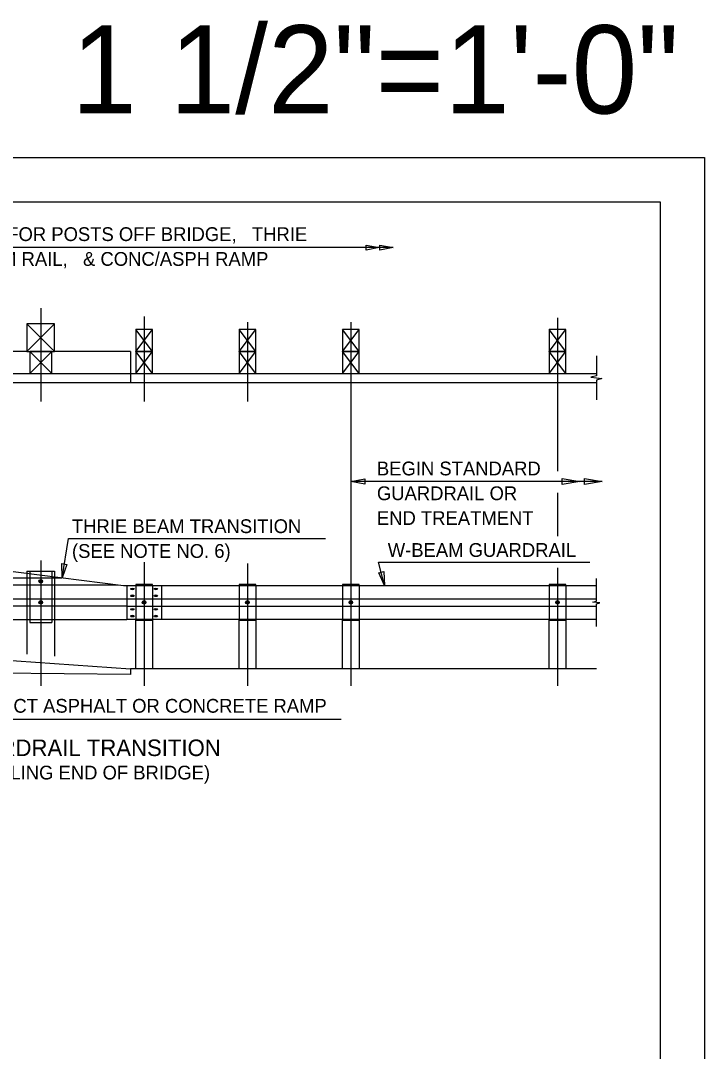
# Model space of a CAD drawing. Extents: x 0 to 22.7, y 0 to 15.7.
# Drawn here: x 17.5 to 22.67, y 7.91 to 15.7 of the extents above; entities that cross this region are included whole.
import ezdxf

# ---------------------------------------------------------------- set-up
doc = ezdxf.new("R2010")
doc.units = 0
for name, color, linetype in [('BORDER_ANNO_Cutsheet', 7, 'Continuous'), ('BRDG_ANNO_Anno-Sheet', 7, 'Continuous'), ('BRDG_ANNO_General-Notes', 7, 'Continuous'), ('BRDG_BASE_Dtlctrln', 7, 'Continuous'), ('BRDG_BASE_Phtline', 7, 'Continuous')]:
    doc.layers.add(name, color=color, linetype=linetype)

msp = doc.modelspace()

# ---------------------------------------------------------------- linework, layer by layer
at = {"layer": 'BORDER_ANNO_Cutsheet'}
msp.add_lwpolyline([(0, 14.6667), (22.6667, 14.6667), (22.6667, 0), (0, 0)], close=True, dxfattribs=at)
at = {"layer": 'BRDG_ANNO_Anno-Sheet'}
msp.add_lwpolyline([(1, 14.3333), (22.3333, 14.3333), (22.3333, 0.3333), (1, 0.3333)], close=True, dxfattribs=at)
at = {"layer": 'BRDG_ANNO_General-Notes'}
for p, q in [((20.3134, 13.9864), (14.4561, 13.9864)), ((20.1093, 13.9677), (20.1093, 14.0052)), ((20.1093, 14.0052), (20.2093, 13.9864)), ((20.2093, 13.9864), (20.1093, 13.9677)), ((20.2134, 13.9677), (20.2134, 14.0052)), ((20.2134, 14.0052), (20.3134, 13.9864)), ((20.3134, 13.9864), (20.2134, 13.9677)), ((19.994, 12.2181), (20.099, 12.2378)), ((20.099, 12.2378), (20.099, 12.1984)), ((21.8945, 12.2181), (19.994, 12.2181)), ((20.099, 12.1984), (19.994, 12.2181)), ((17.8086, 11.5971), (17.8474, 11.5906)), ((17.8107, 11.4903), (17.8086, 11.5971)), ((17.8474, 11.5906), (17.8107, 11.4903)), ((20.2045, 11.5271), (20.2426, 11.5369)), ((20.2426, 11.5369), (20.2498, 11.4303)), ((20.2498, 11.4303), (20.2045, 11.5271)), ((16.7052, 10.4213), (19.9203, 10.4213))]:
    msp.add_line(p, q, dxfattribs=at)
for points in [[(21.5915, 12.2402), (21.7248, 12.2181), (21.5915, 12.1961)], [(21.7611, 12.2402), (21.8945, 12.2181), (21.7611, 12.1961)]]:
    msp.add_lwpolyline(points, close=True, dxfattribs=at)
for points in [[(17.8107, 11.4903), (17.8602, 11.7862), (19.8026, 11.7862)], [(20.2039, 11.6081), (21.7996, 11.6081)], [(20.2498, 11.4303), (20.2039, 11.6081)]]:
    msp.add_lwpolyline(points, dxfattribs=at)
at = {"layer": 'BRDG_BASE_Dtlctrln'}
for p, q in [((17.6502, 13.5289), (17.6502, 12.8218)), ((18.4315, 13.464), (18.4315, 12.8218)), ((19.2127, 13.4211), (19.2127, 12.8218)), ((19.994, 13.4211), (19.994, 10.6736)), ((21.5565, 13.4545), (21.5565, 12.2957)), ((21.5565, 12.1317), (21.5565, 11.8034)), ((17.6502, 11.621), (17.6502, 10.6736)), ((18.4315, 11.6089), (18.4315, 10.6736)), ((19.2127, 11.5986), (19.2127, 10.6736)), ((21.5565, 11.5645), (21.5565, 10.6736))]:
    msp.add_line(p, q, dxfattribs=at)
at = {"layer": 'BRDG_BASE_Phtline'}
for p, q in [((17.546, 13.2011), (17.7544, 13.4095)), ((17.7544, 13.2011), (17.546, 13.4095)), ((18.369, 13.2011), (18.494, 13.3678)), ((18.494, 13.2011), (18.369, 13.3678)), ((19.1502, 13.2011), (19.2752, 13.3678)), ((19.2752, 13.2011), (19.1502, 13.3678)), ((19.9315, 13.2011), (20.0565, 13.3678)), ((20.0565, 13.2011), (19.9315, 13.3678)), ((21.494, 13.2011), (21.619, 13.3678)), ((21.619, 13.2011), (21.494, 13.3678)), ((17.546, 13.2011), (16.9731, 13.2011)), ((17.5669, 13.0345), (17.7335, 13.2011)), ((17.7335, 13.0345), (17.5669, 13.2011)), ((18.3273, 13.2011), (17.7544, 13.2011)), ((18.3273, 13.2011), (18.3273, 13.0345)), ((18.369, 13.0345), (18.494, 13.2011)), ((18.494, 13.0345), (18.369, 13.2011)), ((19.1502, 13.0345), (19.2752, 13.2011)), ((19.2752, 13.0345), (19.1502, 13.2011)), ((19.9315, 13.0345), (20.0565, 13.2011)), ((20.0565, 13.0345), (19.9315, 13.2011)), ((21.494, 13.0345), (21.619, 13.2011)), ((21.619, 13.0345), (21.494, 13.2011)), ((16.7387, 13.0345), (21.8499, 13.0345)), ((18.3273, 13.0345), (18.3273, 12.9668)), ((16.7387, 12.9668), (21.8499, 12.9668)), ((17.0252, 11.5918), (18.2752, 11.4303)), ((17.546, 11.5388), (17.7544, 11.5388)), ((17.546, 11.5388), (17.546, 11.5245)), ((17.5669, 11.5388), (17.5669, 11.5218)), ((17.7335, 11.5388), (17.7335, 11.5003)), ((17.7544, 11.5388), (17.7544, 11.4976)), ((16.9992, 11.4904), (17.8105, 11.4904)), ((17.546, 11.5245), (17.546, 11.1751)), ((17.5669, 11.5218), (17.5669, 11.1751)), ((17.7335, 11.5003), (17.7335, 11.1751)), ((17.7544, 11.4976), (17.7544, 11.1751)), ((16.9992, 11.4354), (18.2359, 11.4354)), ((18.2752, 11.4303), (21.8499, 11.4303)), ((18.3012, 11.4303), (18.3012, 11.1751)), ((18.369, 11.4303), (18.369, 11.1751)), ((18.494, 11.4303), (18.494, 11.1751)), ((18.5617, 11.4303), (18.5617, 11.1751)), ((19.1502, 11.4303), (19.1502, 11.1751)), ((19.2752, 11.4303), (19.2752, 11.1751)), ((19.9315, 11.4303), (19.9315, 11.1751)), ((20.0565, 11.4303), (20.0565, 11.1751)), ((21.494, 11.4303), (21.494, 11.1751)), ((21.619, 11.4303), (21.619, 11.1751)), ((16.9992, 11.3315), (18.3012, 11.3315)), ((18.3012, 11.3302), (21.8499, 11.3302)), ((16.9992, 11.2766), (18.3012, 11.2766)), ((18.3012, 11.2753), (21.8499, 11.2753)), ((16.9992, 11.1751), (18.3012, 11.1751)), ((17.546, 11.1751), (17.546, 10.9115)), ((17.5669, 11.1751), (17.5669, 11.1504)), ((17.5669, 11.1504), (17.7335, 11.1504)), ((17.7335, 11.1751), (17.7335, 11.1504)), ((17.7544, 11.1751), (17.7544, 10.8967)), ((21.8499, 11.1751), (18.3012, 11.1751)), ((18.369, 10.8001), (18.369, 11.166)), ((18.494, 11.166), (18.494, 10.8001)), ((19.1502, 10.8001), (19.1502, 11.166)), ((19.2752, 11.166), (19.2752, 10.8001)), ((19.9315, 10.8001), (19.9315, 11.166)), ((20.0565, 11.166), (20.0565, 10.8001)), ((21.494, 10.8001), (21.494, 11.166)), ((21.619, 11.166), (21.619, 10.8001)), ((15.0244, 11.0356), (18.3273, 10.8001)), ((18.3273, 10.7584), (15.0244, 10.794)), ((21.8499, 10.8001), (18.3273, 10.8001)), ((18.3273, 10.8001), (18.3273, 10.7584))]:
    msp.add_line(p, q, dxfattribs=at)
for points in [[(17.546, 13.2011), (17.7544, 13.2011), (17.7544, 13.4095), (17.546, 13.4095)], [(18.369, 13.2011), (18.494, 13.2011), (18.494, 13.3678), (18.369, 13.3678)], [(19.1502, 13.2011), (19.2752, 13.2011), (19.2752, 13.3678), (19.1502, 13.3678)], [(19.9315, 13.2011), (20.0565, 13.2011), (20.0565, 13.3678), (19.9315, 13.3678)], [(21.494, 13.2011), (21.619, 13.2011), (21.619, 13.3678), (21.494, 13.3678)], [(17.5669, 13.0345), (17.7335, 13.0345), (17.7335, 13.2011), (17.5669, 13.2011)], [(18.369, 13.0345), (18.494, 13.0345), (18.494, 13.2011), (18.369, 13.2011)], [(19.1502, 13.0345), (19.2752, 13.0345), (19.2752, 13.2011), (19.1502, 13.2011)], [(19.9315, 13.0345), (20.0565, 13.0345), (20.0565, 13.2011), (19.9315, 13.2011)], [(21.494, 13.0345), (21.619, 13.0345), (21.619, 13.2011), (21.494, 13.2011)]]:
    msp.add_lwpolyline(points, close=True, dxfattribs=at)
for points in [[(21.8499, 13.1673), (21.8499, 13.0162), (21.8082, 13.0058), (21.8499, 13.0006), (21.8916, 12.9954), (21.8499, 12.985), (21.8499, 12.834)], [(21.8499, 11.1204), (21.8499, 11.293), (21.8759, 11.2995), (21.8499, 11.3027), (21.8239, 11.306), (21.8499, 11.3125), (21.8499, 11.485)], [(18.494, 11.4303), (18.494, 11.4394), (18.369, 11.4394), (18.369, 11.4303)], [(19.2752, 11.4303), (19.2752, 11.4394), (19.1502, 11.4394), (19.1502, 11.4303)], [(20.0565, 11.4303), (20.0565, 11.4394), (19.9315, 11.4394), (19.9315, 11.4303)], [(21.619, 11.4303), (21.619, 11.4394), (21.494, 11.4394), (21.494, 11.4303)], [(18.494, 11.1751), (18.494, 11.166), (18.369, 11.166), (18.369, 11.1751)], [(19.2752, 11.1751), (19.2752, 11.166), (19.1502, 11.166), (19.1502, 11.1751)], [(20.0565, 11.1751), (20.0565, 11.166), (19.9315, 11.166), (19.9315, 11.1751)], [(21.619, 11.1751), (21.619, 11.166), (21.494, 11.166), (21.494, 11.1751)]]:
    msp.add_lwpolyline(points, dxfattribs=at)
for centre, radius in [((17.6502, 11.4629), 0.0137), ((17.6502, 11.4629), 0.00651), ((17.6502, 11.304), 0.0137), ((17.6502, 11.304), 0.00651), ((18.4314, 11.304), 0.0137), ((18.4314, 11.304), 0.00651), ((19.2127, 11.304), 0.0137), ((19.2127, 11.304), 0.00651), ((19.9939, 11.304), 0.0137), ((19.9939, 11.304), 0.00651), ((21.5564, 11.304), 0.0137), ((21.5564, 11.304), 0.00651)]:
    msp.add_circle(centre, radius, dxfattribs=at)
for centre, major_axis, ratio in [((17.6502, 11.4629), (0, 0.00977), 0.666667), ((18.3429, 11.405), (0.0137, 0), 0.5), ((18.3429, 11.405), (0.00651, 0), 0.75), ((18.3429, 11.405), (0.00651, 0), 0.5), ((18.52, 11.405), (0.0137, 0), 0.5), ((18.52, 11.405), (0.00651, 0), 0.75), ((18.52, 11.405), (0.00651, 0), 0.5), ((17.6502, 11.304), (0, 0.00977), 0.666667), ((18.3429, 11.3542), (0.0137, 0), 0.5), ((18.3429, 11.3542), (0.00651, 0), 0.75), ((18.3429, 11.3542), (0.00651, 0), 0.5), ((18.4314, 11.304), (0, 0.00977), 0.666667), ((18.52, 11.3542), (0.0137, 0), 0.5), ((18.52, 11.3542), (0.00651, 0), 0.75), ((18.52, 11.3542), (0.00651, 0), 0.5), ((19.2127, 11.304), (0, 0.00977), 0.666667), ((19.9939, 11.304), (0, 0.00977), 0.666667), ((21.5564, 11.304), (0, 0.00977), 0.666667), ((18.3429, 11.2512), (0.0137, 0), 0.5), ((18.3429, 11.2512), (-0.00651, 0), 0.75), ((18.3429, 11.2512), (0.00651, 0), 0.5), ((18.52, 11.2512), (0.0137, 0), 0.5), ((18.52, 11.2512), (-0.00651, 0), 0.75), ((18.52, 11.2512), (0.00651, 0), 0.5), ((18.3429, 11.2005), (0.0137, 0), 0.5), ((18.3429, 11.2005), (-0.00651, 0), 0.75), ((18.3429, 11.2005), (0.00651, 0), 0.5), ((18.52, 11.2005), (0.0137, 0), 0.5), ((18.52, 11.2005), (-0.00651, 0), 0.75), ((18.52, 11.2005), (0.00651, 0), 0.5)]:
    msp.add_ellipse(centre, major_axis=major_axis, ratio=ratio, dxfattribs=at)

# ---------------------------------------------------------------- texts
at = {"layer": 'BRDG_ANNO_Anno-Sheet'}
msp.add_text('1 1/2"=1\'-0"', height=0.666667, dxfattribs=at).set_placement((17.8808, 15))
at = {"layer": 'BRDG_ANNO_General-Notes'}
for s, height, p in [('ROADWAY PAY ITEM LIMITS FOR POSTS OFF BRIDGE,   THRIE', 0.104167, (15.4621, 14.0357)), ('BEAM TRANSITION,   W-BEAM RAIL,   & CONC/ASPH RAMP', 0.104167, (15.4621, 13.8482)), ('BEGIN STANDARD ', 0.104167, (20.1913, 12.264)), ('GUARDRAIL OR ', 0.104167, (20.1913, 12.0765)), ('THRIE BEAM TRANSITION', 0.104167, (17.886, 11.8276)), ('END TREATMENT', 0.104167, (20.1913, 11.889)), ('(SEE NOTE NO. 6)', 0.104167, (17.886, 11.6401)), ('W-BEAM GUARDRAIL', 0.104167, (20.2731, 11.6477)), ('CONSTRUCT ASPHALT OR CONCRETE RAMP', 0.104167, (16.7546, 10.4696)), ('THRIE BEAM TO W-BEAM GUARDRAIL TRANSITION', 0.125, (14.8963, 10.1419)), ('(TYPICAL FOR APPROACH AND TRAILING END OF BRIDGE)', 0.104167, (14.9517, 9.9648))]:
    msp.add_text(s, height=height, dxfattribs=at).set_placement(p)

doc.saveas('drawing.dxf')
